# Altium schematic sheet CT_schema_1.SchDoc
size 515 x 464 mm
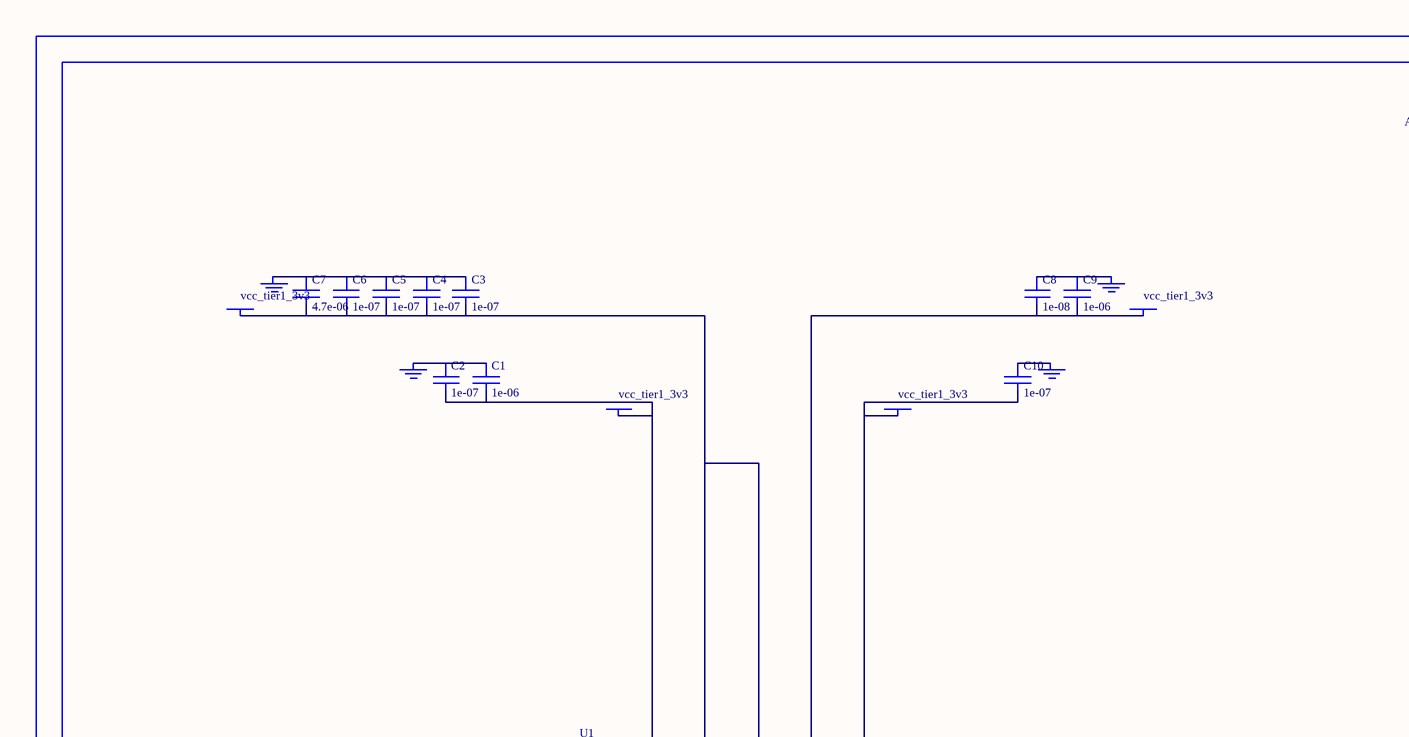
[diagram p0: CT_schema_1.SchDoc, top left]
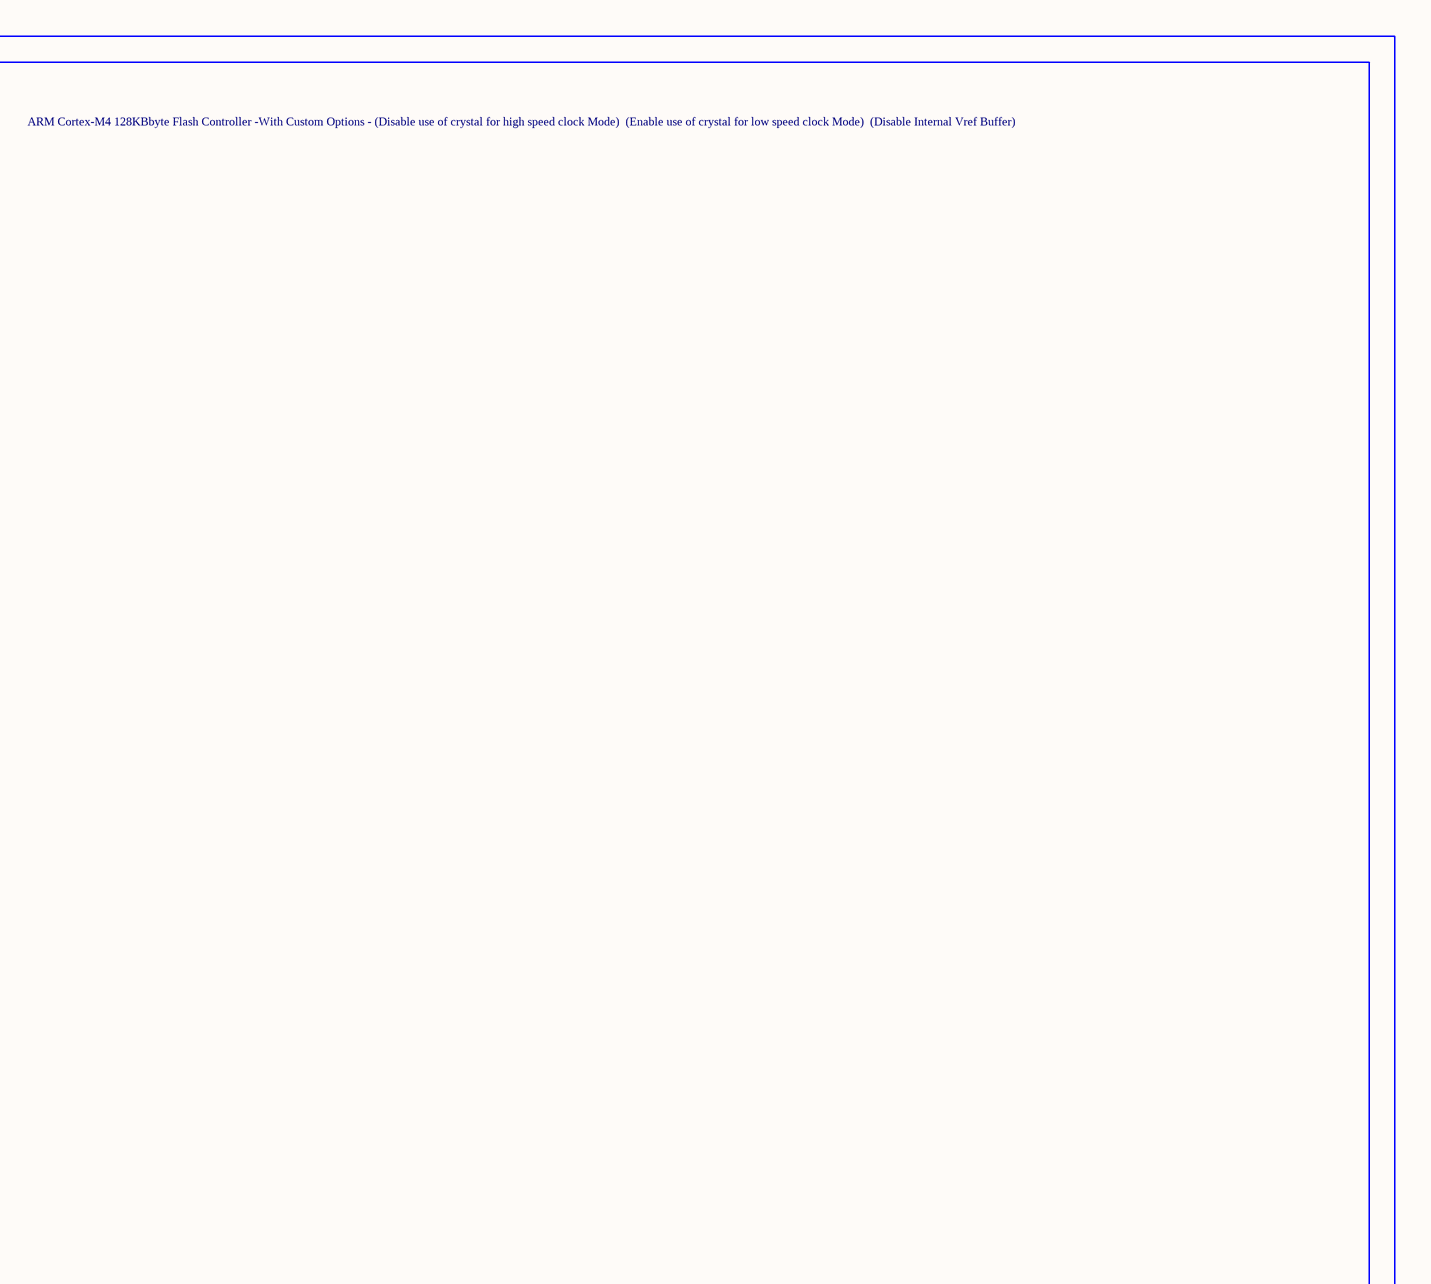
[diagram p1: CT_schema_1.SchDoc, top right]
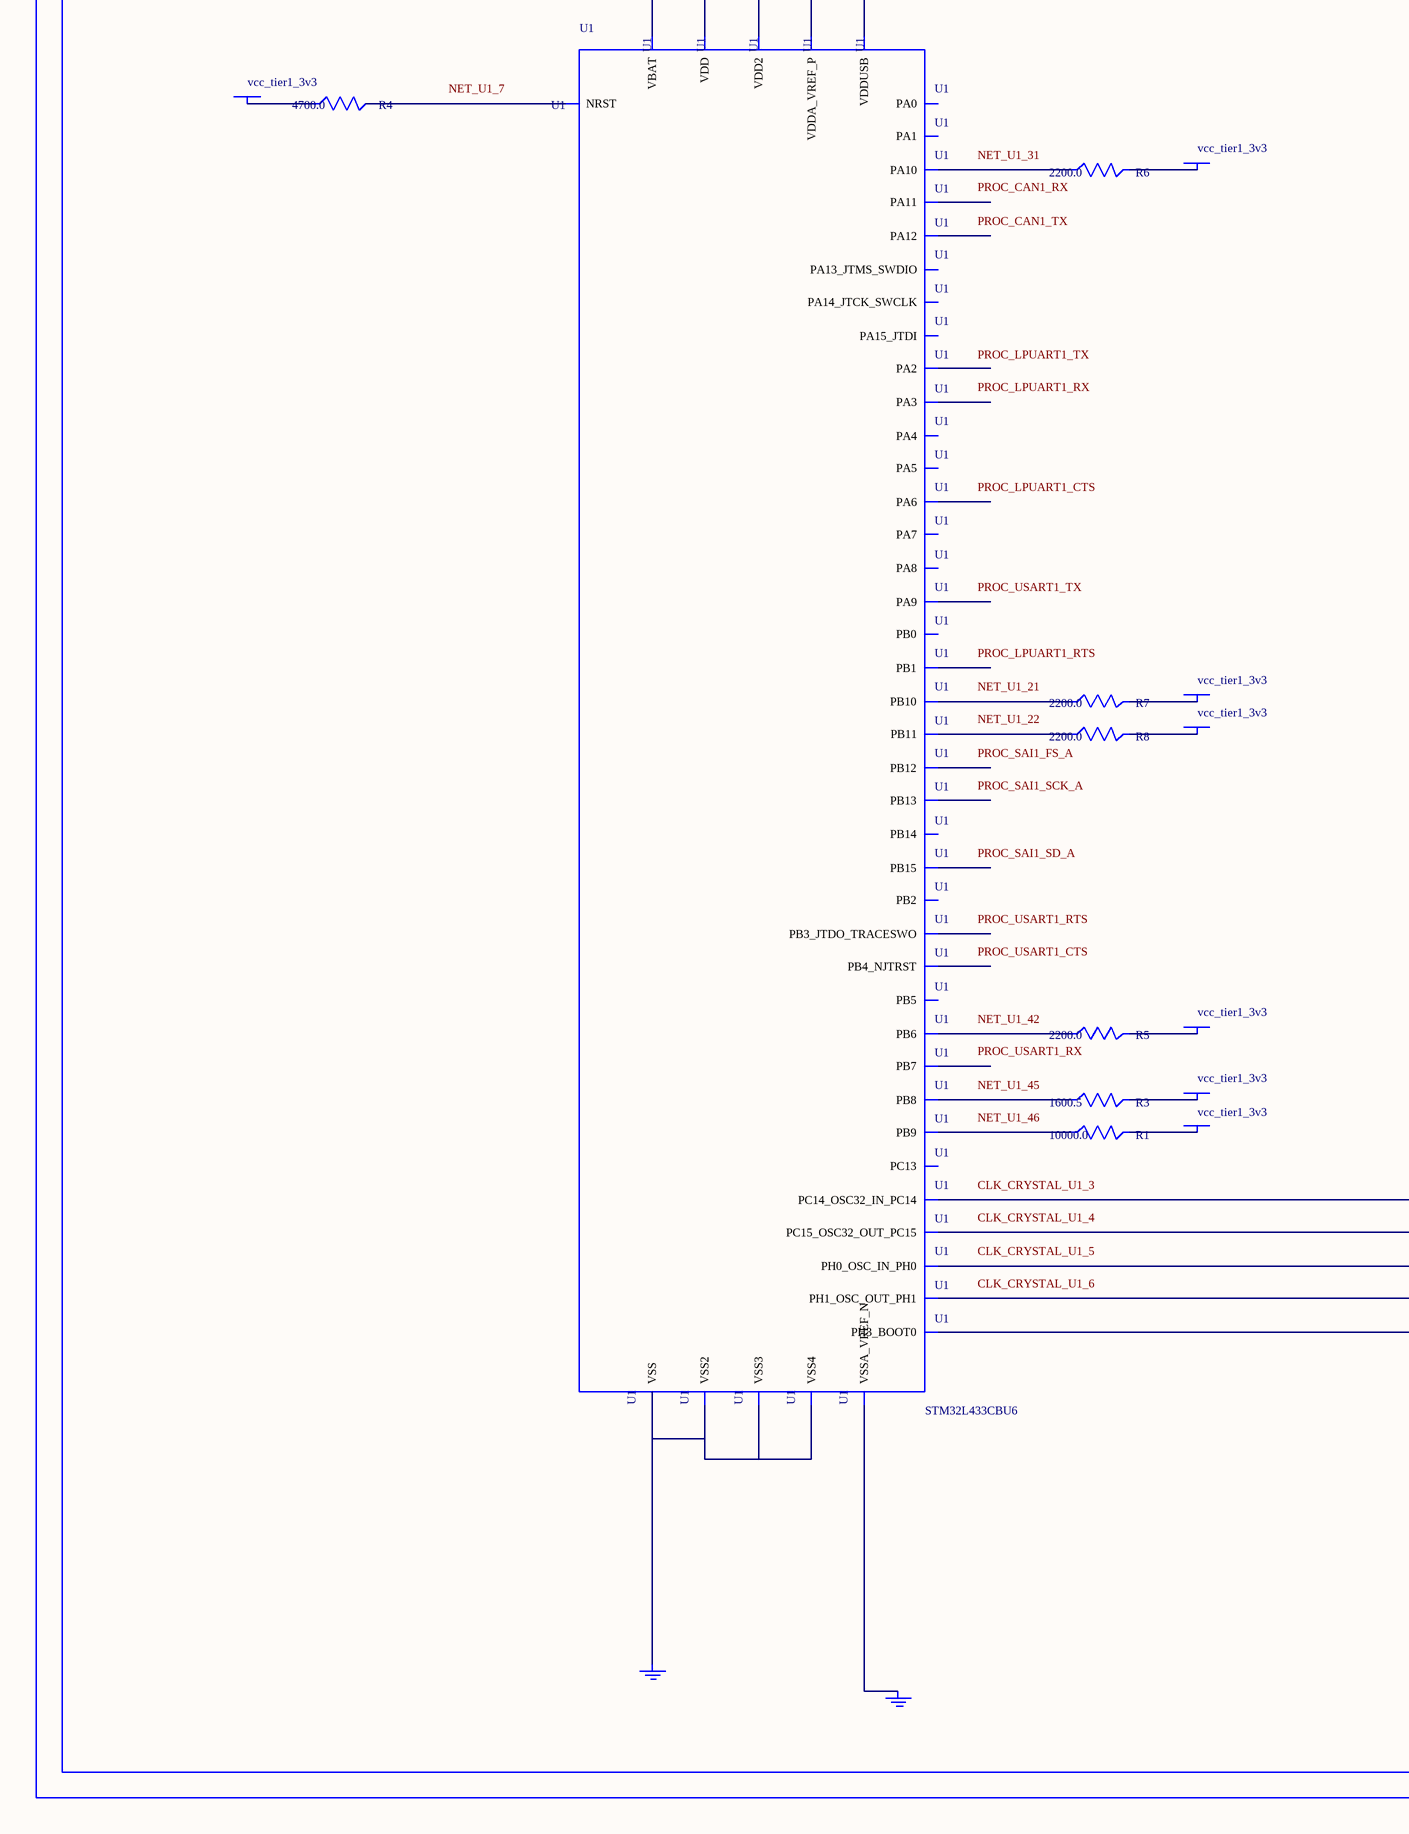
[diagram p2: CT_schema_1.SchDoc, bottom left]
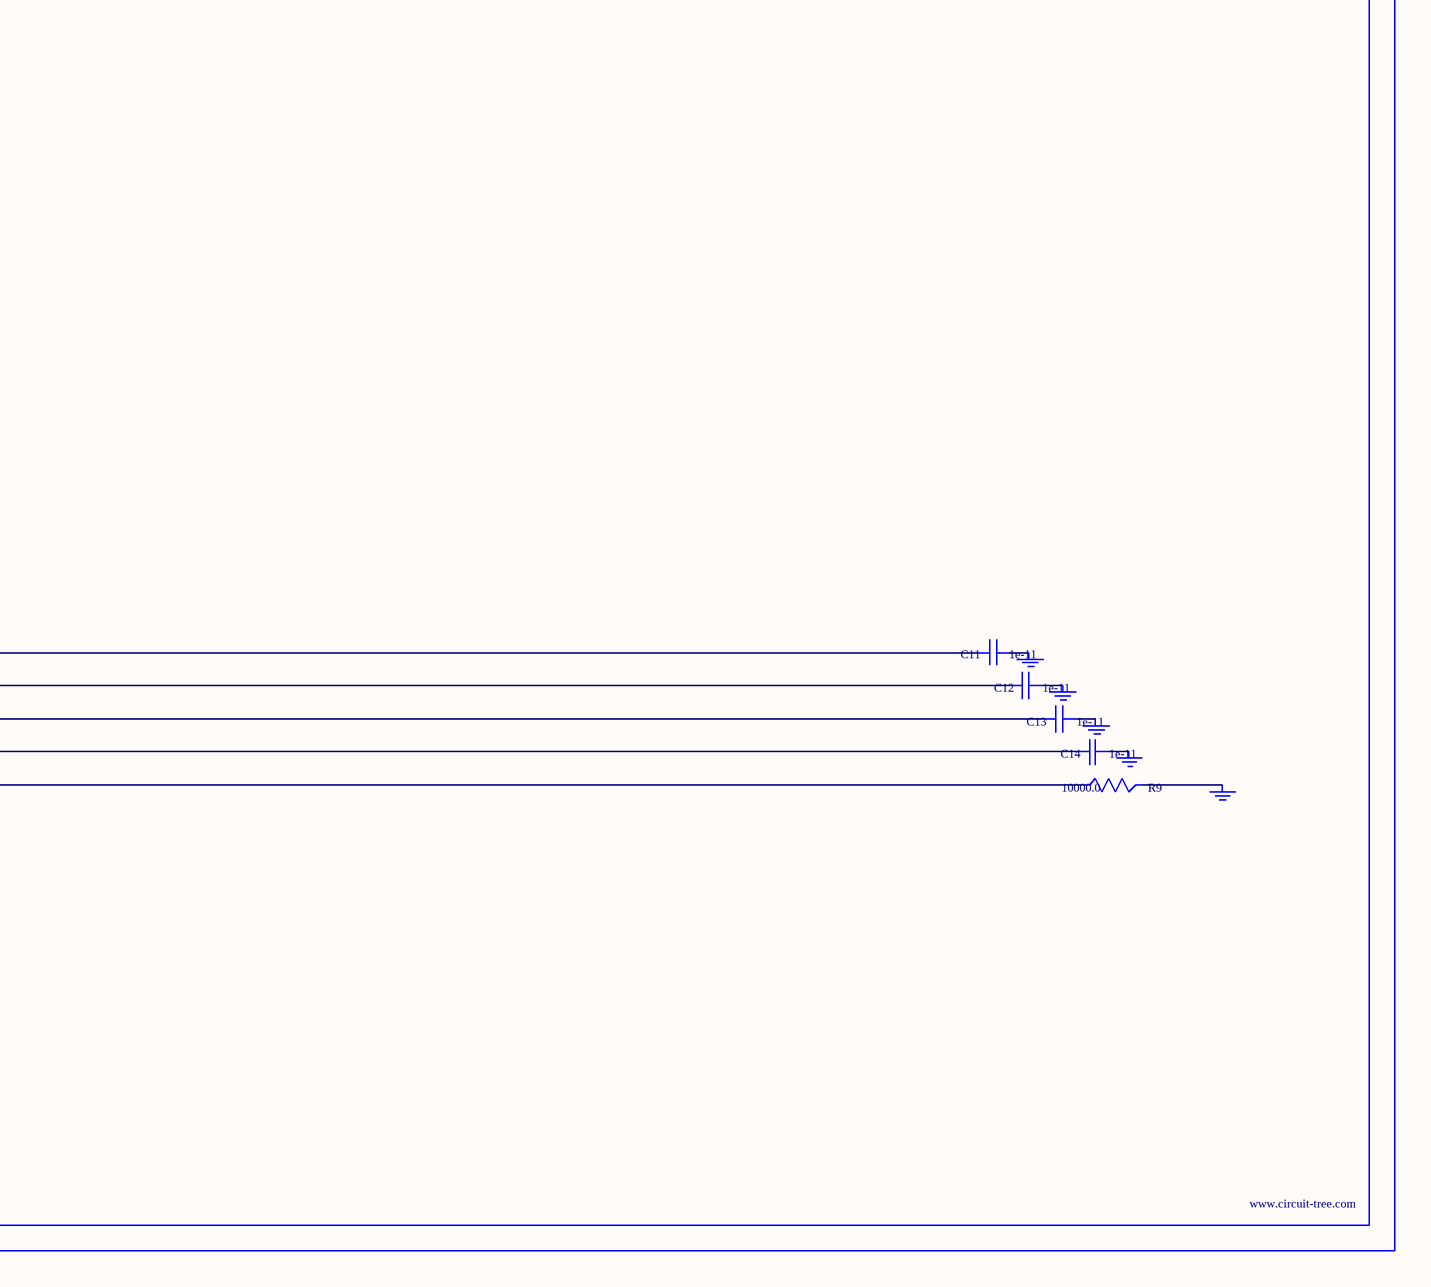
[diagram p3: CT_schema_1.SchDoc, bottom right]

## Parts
BORDER0  (no value)
C1  1e-06  [C0603]
C2  1e-07  [C0603]
C3  1e-07  [C0603]
C4  1e-07  [C0603]
C5  1e-07  [C0603]
C6  1e-07  [C0603]
C7  4.7e-06  [C0603]
C8  1e-08  [C0603]
C9  1e-06  [C0603]
C10  1e-07  [C0603]
C11  1e-11  [C0402]
C12  1e-11  [C0402]
C13  1e-11  [C0402]
C14  1e-11  [C0402]
GND_INSTANCE_0_0  (no value)
GND_INSTANCE_0_1  (no value)
GND_INSTANCE_0_2  (no value)
GND_INSTANCE_0_3  (no value)
GND_INSTANCE_0_4  (no value)
GND_INSTANCE_0_5  (no value)
GND_INSTANCE_0_6  (no value)
GND_INSTANCE_0_7  (no value)
GND_INSTANCE_0_8  (no value)
GND_INSTANCE_0_9  (no value)
GND_INSTANCE_0_10  (no value)
POWER_INSTANCE_0_0  vcc_tier1_3v3
POWER_INSTANCE_0_1  vcc_tier1_3v3
POWER_INSTANCE_0_2  vcc_tier1_3v3
POWER_INSTANCE_0_3  vcc_tier1_3v3
POWER_INSTANCE_0_4  vcc_tier1_3v3
POWER_INSTANCE_0_5  vcc_tier1_3v3
POWER_INSTANCE_0_6  vcc_tier1_3v3
POWER_INSTANCE_0_7  vcc_tier1_3v3
POWER_INSTANCE_0_8  vcc_tier1_3v3
POWER_INSTANCE_0_9  vcc_tier1_3v3
POWER_INSTANCE_0_10  vcc_tier1_3v3
R1  10000.0  [R0603]
R3  1600.5  [R0603]
R4  4700.0  [R0603]
R5  2200.0  [R0603]
R6  2200.0  [R0603]
R7  2200.0  [R0603]
R8  2200.0  [R0603]
R9  10000.0  [R0603]
U1  STM32L433CBU6  [UFQFPN48]

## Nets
NetC1_1: C1.1 C2.1 GND_INSTANCE_0_0.0(GND)
NetC1_2: C1.2 C2.2 POWER_INSTANCE_0_0.0(PWR) U1.1(VBAT)
NetC3_1: C3.1 C4.1 C5.1 C6.1 C7.1 GND_INSTANCE_0_7.0(GND)
NetC3_2: C3.2 C4.2 C5.2 C6.2 C7.2 POWER_INSTANCE_0_2.0(PWR) U1.24(VDD) U1.48(VDD2)
NetC8_1: C8.1 C9.1 GND_INSTANCE_0_6.0(GND)
NetC8_2: C8.2 C9.2 POWER_INSTANCE_0_1.0(PWR) U1.9(VDDA_VREF_P)
NetC10_1: C10.1 GND_INSTANCE_0_8.0(GND)
NetC10_2: C10.2 POWER_INSTANCE_0_3.0(PWR) U1.36(VDDUSB)
NetC11_1: C11.1 GND_INSTANCE_0_1.0(GND)
NetC11_2: C11.2 U1.3(PC14_OSC32_IN_PC14)
NetC12_1: C12.1 GND_INSTANCE_0_2.0(GND)
NetC12_2: C12.2 U1.4(PC15_OSC32_OUT_PC15)
NetC13_1: C13.1 GND_INSTANCE_0_3.0(GND)
NetC13_2: C13.2 U1.5(PH0_OSC_IN_PH0)
NetC14_1: C14.1 GND_INSTANCE_0_4.0(GND)
NetC14_2: C14.2 U1.6(PH1_OSC_OUT_PH1)
NetGND_INSTANCE_0_5_0: GND_INSTANCE_0_5.0(GND) U1.8(VSSA_VREF_N)
NetGND_INSTANCE_0_9_0: GND_INSTANCE_0_9.0(GND) R9.2
NetGND_INSTANCE_0_10_0: GND_INSTANCE_0_10.0(GND) U1.23(VSS) U1.35(VSS2) U1.47(VSS3) U1.49(VSS4)
NetPOWER_INSTANCE_0_4_0: POWER_INSTANCE_0_4.0(PWR) R4.1
NetPOWER_INSTANCE_0_5_0: POWER_INSTANCE_0_5.0(PWR) R7.2
NetPOWER_INSTANCE_0_6_0: POWER_INSTANCE_0_6.0(PWR) R8.2
NetPOWER_INSTANCE_0_7_0: POWER_INSTANCE_0_7.0(PWR) R6.2
NetPOWER_INSTANCE_0_8_0: POWER_INSTANCE_0_8.0(PWR) R5.2
NetPOWER_INSTANCE_0_9_0: POWER_INSTANCE_0_9.0(PWR) R3.2
NetPOWER_INSTANCE_0_10_0: POWER_INSTANCE_0_10.0(PWR) R1.2
NetR1_1: R1.1 U1.46(PB9)
NetR3_1: R3.1 U1.45(PB8)
NetR4_2: R4.2 U1.7(NRST)
NetR5_1: R5.1 U1.42(PB6)
NetR6_1: R6.1 U1.31(PA10)
NetR7_1: R7.1 U1.21(PB10)
NetR8_1: R8.1 U1.22(PB11)
NetR9_1: R9.1 U1.44(PH3_BOOT0)

Not connected (* = marked no-connect by the designer): U1 2(PC13) 10(PA0) 11(PA1) 12(PA2) 13(PA3) 14(PA4) 15(PA5) 16(PA6) 17(PA7) 18(PB0) 19(PB1) 20(PB2) 25(PB12) 26(PB13) 27(PB14) 28(PB15) 29(PA8) 30(PA9) 32(PA11) 33(PA12) 34(PA13_JTMS_SWDIO) 37(PA14_JTCK_SWCLK) 38(PA15_JTDI) 39(PB3_JTDO_TRACESWO) 40(PB4_NJTRST) 41(PB5) 43(PB7)

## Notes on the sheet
- Labels drawn without touching a wire or pin: CLK_CRYSTAL_U1_3, CLK_CRYSTAL_U1_4, CLK_CRYSTAL_U1_5, CLK_CRYSTAL_U1_6, NET_U1_7, NET_U1_21, NET_U1_22, NET_U1_31, NET_U1_42, NET_U1_45, NET_U1_46, PROC_CAN1_RX, PROC_CAN1_TX, PROC_LPUART1_CTS, PROC_LPUART1_RTS, PROC_LPUART1_RX, PROC_LPUART1_TX, PROC_SAI1_FS_A, PROC_SAI1_SCK_A, PROC_SAI1_SD_A, PROC_USART1_CTS, PROC_USART1_RTS, PROC_USART1_RX, PROC_USART1_TX

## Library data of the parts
BORDER0 = BORDER_PAGE0
C1 C9 = C0603C105K3RACTU
C2-C6 C10 = 06035C104K4Z2A
C7 = GRM188R6YA475KE15D
C8 = 06035C103K4Z2A
C11-C14 = C0402C100K3GACTU
GND_INSTANCE_0_0-GND_INSTANCE_0_10 = GND
POWER_INSTANCE_0_0-POWER_INSTANCE_0_10 = PWR
R1 R9 = RC0603JR-0710KL
R3 = R3
R4 = RC0603JR-074K7L
R5-R8 = RC0603JR-072K2L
